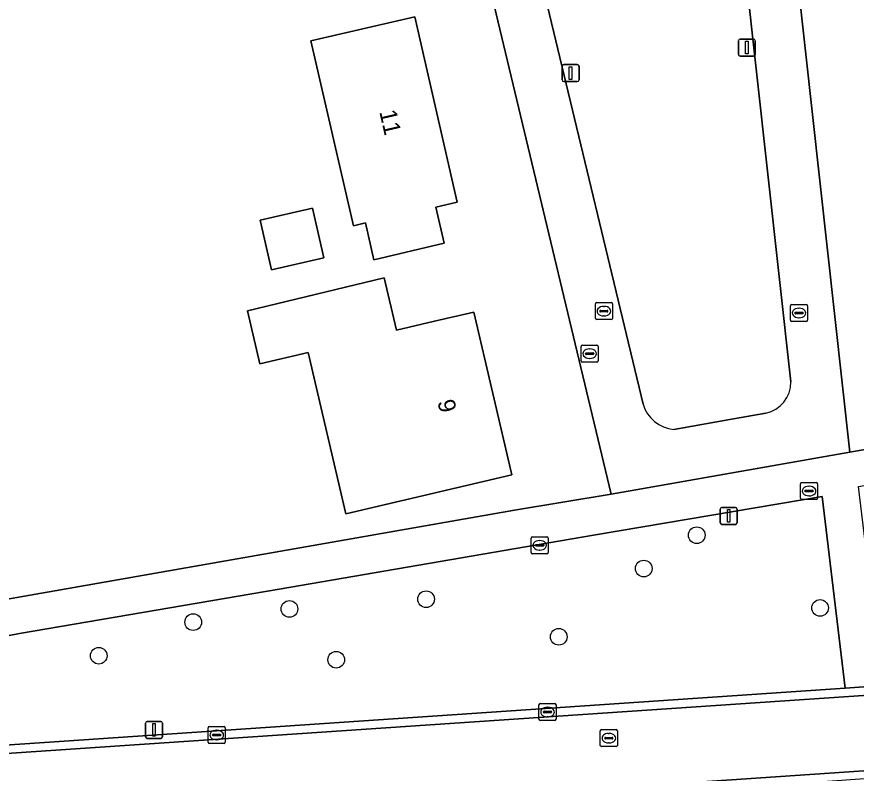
# Model space of a CAD drawing. Extents: x 162661 to 163484, y 380247 to 381230.
# Drawn here: x 162957.93 to 163007.21, y 380348.4 to 380392.8 of the extents above; entities that cross this region are included whole.
import ezdxf

# ---------------------------------------------------------------- set-up
doc = ezdxf.new("R2010")
doc.units = 0
for name, color, linetype in [('IMGEO_Boom', 7, 'Continuous'), ('IMGEO_Brandkraan', 7, 'Continuous'), ('IMGEO_Erf', 7, 'Continuous'), ('IMGEO_Groenvoorziening', 7, 'Continuous'), ('IMGEO_Kolk', 7, 'Continuous'), ('IMGEO_Lichtmast', 7, 'Continuous'), ('IMGEO_Pand', 7, 'Continuous'), ('IMGEO_Pand_nummerreeks', 7, 'Continuous'), ('IMGEO_Rijbaan_lokaal_gesloten', 7, 'Continuous'), ('IMGEO_Rijbaan_lokaal_open', 7, 'Continuous'), ('IMGEO_Rioolput', 7, 'Continuous'), ('IMGEO_Voetpad_open', 7, 'Continuous')]:
    doc.layers.add(name, color=color, linetype=linetype)

msp = doc.modelspace()

# ---------------------------------------------------------------- linework, layer by layer
at = {"layer": 'IMGEO_Boom'}
for centre in [(162997.848, 380362.374), (162994.736, 380360.416), (162981.956, 380358.616), (162973.936, 380358.043), (163005.09, 380358.105), (162968.286, 380357.27), (162989.744, 380356.409), (162962.74, 380355.298), (162976.682, 380355.067)]:
    msp.add_circle(centre, 0.489, dxfattribs=at)
at = {"layer": 'IMGEO_Brandkraan'}
for p, q in [((162991.059, 380372.602), (162991.059, 380373.454)), ((162991.134, 380373.528), (162991.986, 380373.528)), ((162991.547, 380373.308), (162991.572, 380373.308)), ((162992.06, 380373.454), (162992.06, 380372.602)), ((162991.318, 380373.022), (162991.318, 380373.034)), ((162991.756, 380372.985), (162991.358, 380372.985)), ((162991.361, 380373.071), (162991.759, 380373.071)), ((162991.802, 380373.034), (162991.802, 380373.022)), ((162991.986, 380372.528), (162991.134, 380372.528)), ((162991.57, 380372.748), (162991.545, 380372.748))]:
    msp.add_line(p, q, dxfattribs=at)
for points in [[(162991.059, 380372.602), (162991.059, 380373.454)], [(162991.134, 380373.528), (162991.986, 380373.528)], [(162992.06, 380373.454), (162992.06, 380372.602)], [(162991.986, 380372.528), (162991.134, 380372.528)]]:
    msp.add_lwpolyline(points, dxfattribs=at)
for centre, radius, start, end in [((162991.136, 380373.452), 0.0765, 91.552, 178.448), ((162991.136, 380373.452), 0.0765, 91.552, 178.448), ((162991.984, 380373.452), 0.0765, 1.552, 88.448), ((162991.984, 380373.452), 0.0765, 1.552, 88.448), ((162991.358, 380373.031), 0.0403, 85.8775, 175.7526), ((162991.355, 380373.021), 0.0366, 178.938, 274.7102), ((162991.759, 380373.028), 0.043, 264.8664, 352.4533), ((162991.763, 380373.033), 0.0386, 1.7309, 96.639), ((162991.136, 380372.604), 0.0765, 181.552, 268.448), ((162991.136, 380372.604), 0.0765, 181.552, 268.448), ((162991.984, 380372.604), 0.0765, 271.552, 358.448), ((162991.984, 380372.604), 0.0765, 271.552, 358.448)]:
    msp.add_arc(centre, radius, start, end, dxfattribs=at)
for centre, major_axis, ratio, start_param, end_param in [((162991.546, 380373.028), (-0.387, 0.002), 0.722429, 4.712389, 7.853982), ((162991.571, 380373.028), (-0.39, 0.002), 0.717154, 1.570796, 4.712389)]:
    msp.add_ellipse(centre, major_axis=major_axis, ratio=ratio, start_param=start_param, end_param=end_param, dxfattribs=at)
at = {"layer": 'IMGEO_Erf'}
for points in [[(163047.603, 380433.152), (163037.976, 380431.448), (163035.606, 380431.035), (163000.273, 380424.875), (163000.715, 380422.638), (163006.844, 380367.252), (163011.947, 380368.147), (163056.95, 380375.873)], [(162978.403, 380380.697), (162977.693, 380380.534), (162975.198, 380391.388), (162981.296, 380392.79), (162983.793, 380381.919), (162982.534, 380381.629), (162983.018, 380379.52), (162978.9, 380378.536)], [(162972.219, 380380.862), (162975.285, 380381.566), (162975.954, 380378.655), (162972.889, 380377.95)], [(162979.492, 380377.472), (162980.227, 380374.409), (162982.452, 380374.94), (162984.767, 380375.463), (162986.986, 380365.917), (162977.24, 380363.634), (162975.026, 380373.087), (162972.2, 380372.426), (162971.47, 380375.545)]]:
    msp.add_lwpolyline(points, close=True, dxfattribs=at)
msp.add_lwpolyline([(162943.939, 380397.468), (162945.155, 380386.295), (162946.371, 380375.13), (162945.703, 380375.057), (162945.909, 380373.16), (162946.16, 380370.851), (162946.868, 380370.928), (162948.049, 380360.077), (162951.696, 380360.474), (162952.002, 380357.671), (162987.152, 380363.833), (162992.818, 380364.786), (162980.426, 380416.595)], dxfattribs=at)
at = {"layer": 'IMGEO_Groenvoorziening'}
for points in [[(163003.383, 380371.369), (163000, 380401.781), (162997.93, 380419.975), (162997.616, 380422.36), (162997.043, 380422.281), (162983.247, 380419.922), (162982.667, 380419.816), (162983.47, 380416.805), (162994.695, 380370.063)], [(162996.513, 380368.584), (163000, 380369.199), (163001.901, 380369.535)], [(162940.787, 380348.935), (163006.568, 380353.401), (163005.21, 380364.635), (163000, 380363.76), (162991.897, 380362.399), (162989.055, 380361.908), (162973.327, 380359.209), (162958.085, 380356.605), (162953.727, 380355.77), (162950.999, 380355.403), (162937.978, 380353.182), (162938.144, 380351.678)]]:
    msp.add_lwpolyline(points, dxfattribs=at)
for centre, radius, start, end in [((163001.524, 380371.355), 1.859, 281.6989, 0.4199), ((162996.683, 380370.65), 2.073, 196.4576, 265.2836)]:
    msp.add_arc(centre, radius, start, end, dxfattribs=at)
at = {"layer": 'IMGEO_Kolk'}
for p, q in [((163003.944, 380364.537), (163003.944, 380365.389)), ((163004.019, 380365.463), (163004.871, 380365.463)), ((163004.945, 380365.389), (163004.945, 380364.537)), ((163004.203, 380364.957), (163004.203, 380364.969)), ((163004.641, 380364.92), (163004.243, 380364.92)), ((163004.246, 380365.006), (163004.644, 380365.006)), ((163004.432, 380365.243), (163004.457, 380365.243)), ((163004.687, 380364.969), (163004.687, 380364.957)), ((163004.871, 380364.463), (163004.019, 380364.463)), ((163004.455, 380364.683), (163004.43, 380364.683)), ((162988.125, 380361.355), (162988.125, 380362.207)), ((162988.2, 380362.281), (162989.052, 380362.281)), ((162988.613, 380362.061), (162988.638, 380362.061)), ((162989.126, 380362.207), (162989.126, 380361.355)), ((162988.384, 380361.775), (162988.384, 380361.787)), ((162988.822, 380361.738), (162988.424, 380361.738)), ((162988.427, 380361.824), (162988.825, 380361.824)), ((162988.636, 380361.501), (162988.611, 380361.501)), ((162988.868, 380361.787), (162988.868, 380361.775)), ((162989.052, 380361.281), (162988.2, 380361.281)), ((162988.587, 380351.568), (162988.587, 380352.42)), ((162988.662, 380352.494), (162989.514, 380352.494)), ((162989.075, 380352.274), (162989.1, 380352.274)), ((162989.588, 380352.42), (162989.588, 380351.568)), ((162988.846, 380351.988), (162988.846, 380352)), ((162989.284, 380351.951), (162988.886, 380351.951)), ((162988.889, 380352.037), (162989.287, 380352.037)), ((162989.098, 380351.714), (162989.073, 380351.714)), ((162989.33, 380352), (162989.33, 380351.988)), ((162969.242, 380351.144), (162970.094, 380351.144)), ((162989.514, 380351.494), (162988.662, 380351.494)), ((162969.167, 380350.218), (162969.167, 380351.07)), ((162969.426, 380350.638), (162969.426, 380350.65)), ((162969.864, 380350.601), (162969.466, 380350.601)), ((162969.469, 380350.687), (162969.867, 380350.687)), ((162969.655, 380350.924), (162969.68, 380350.924)), ((162969.91, 380350.65), (162969.91, 380350.638)), ((162970.168, 380351.07), (162970.168, 380350.218)), ((162970.094, 380350.144), (162969.242, 380350.144)), ((162969.678, 380350.364), (162969.653, 380350.364))]:
    msp.add_line(p, q, dxfattribs=at)
for points in [[(163003.944, 380364.537), (163003.944, 380365.389)], [(163004.019, 380365.463), (163004.871, 380365.463)], [(163004.945, 380365.389), (163004.945, 380364.537)], [(163004.871, 380364.463), (163004.019, 380364.463)], [(162988.125, 380361.355), (162988.125, 380362.207)], [(162988.2, 380362.281), (162989.052, 380362.281)], [(162989.126, 380362.207), (162989.126, 380361.355)], [(162989.052, 380361.281), (162988.2, 380361.281)], [(162988.587, 380351.568), (162988.587, 380352.42)], [(162988.662, 380352.494), (162989.514, 380352.494)], [(162989.588, 380352.42), (162989.588, 380351.568)], [(162969.242, 380351.144), (162970.094, 380351.144)], [(162989.514, 380351.494), (162988.662, 380351.494)], [(162969.167, 380350.218), (162969.167, 380351.07)], [(162970.168, 380351.07), (162970.168, 380350.218)], [(162970.094, 380350.144), (162969.242, 380350.144)]]:
    msp.add_lwpolyline(points, dxfattribs=at)
for centre, radius, start, end in [((163004.021, 380365.387), 0.0765, 91.552, 178.448), ((163004.021, 380365.387), 0.0765, 91.552, 178.448), ((163004.869, 380365.387), 0.0765, 1.552, 88.448), ((163004.869, 380365.387), 0.0765, 1.552, 88.448), ((163004.243, 380364.966), 0.0403, 85.8775, 175.7526), ((163004.24, 380364.956), 0.0366, 178.938, 274.7102), ((163004.644, 380364.963), 0.043, 264.8664, 352.4533), ((163004.648, 380364.968), 0.0386, 1.7309, 96.639), ((163004.021, 380364.539), 0.0765, 181.552, 268.448), ((163004.021, 380364.539), 0.0765, 181.552, 268.448), ((163004.869, 380364.539), 0.0765, 271.552, 358.448), ((163004.869, 380364.539), 0.0765, 271.552, 358.448), ((162988.202, 380362.205), 0.0765, 91.552, 178.448), ((162988.202, 380362.205), 0.0765, 91.552, 178.448), ((162989.05, 380362.205), 0.0765, 1.552, 88.448), ((162989.05, 380362.205), 0.0765, 1.552, 88.448), ((162988.424, 380361.784), 0.0403, 85.8775, 175.7526), ((162988.421, 380361.774), 0.0366, 178.938, 274.7102), ((162988.825, 380361.781), 0.043, 264.8664, 352.4533), ((162988.829, 380361.786), 0.0386, 1.7309, 96.639), ((162988.202, 380361.357), 0.0765, 181.552, 268.448), ((162988.202, 380361.357), 0.0765, 181.552, 268.448), ((162989.05, 380361.357), 0.0765, 271.552, 358.448), ((162989.05, 380361.357), 0.0765, 271.552, 358.448), ((162988.664, 380352.418), 0.0765, 91.552, 178.448), ((162988.664, 380352.418), 0.0765, 91.552, 178.448), ((162989.512, 380352.418), 0.0765, 1.552, 88.448), ((162989.512, 380352.418), 0.0765, 1.552, 88.448), ((162988.664, 380351.57), 0.0765, 181.552, 268.448), ((162988.664, 380351.57), 0.0765, 181.552, 268.448), ((162988.886, 380351.997), 0.0403, 85.8775, 175.7526), ((162988.883, 380351.987), 0.0366, 178.938, 274.7102), ((162989.287, 380351.994), 0.043, 264.8664, 352.4533), ((162989.291, 380351.999), 0.0386, 1.7309, 96.639), ((162989.512, 380351.57), 0.0765, 271.552, 358.448), ((162989.512, 380351.57), 0.0765, 271.552, 358.448), ((162969.244, 380351.068), 0.0765, 91.552, 178.448), ((162969.244, 380351.068), 0.0765, 91.552, 178.448), ((162970.092, 380351.068), 0.0765, 1.552, 88.448), ((162970.092, 380351.068), 0.0765, 1.552, 88.448), ((162969.466, 380350.647), 0.0403, 85.8775, 175.7526), ((162969.463, 380350.637), 0.0366, 178.938, 274.7102), ((162969.867, 380350.644), 0.043, 264.8664, 352.4533), ((162969.871, 380350.649), 0.0386, 1.7309, 96.639), ((162969.244, 380350.22), 0.0765, 181.552, 268.448), ((162969.244, 380350.22), 0.0765, 181.552, 268.448), ((162970.092, 380350.22), 0.0765, 271.552, 358.448), ((162970.092, 380350.22), 0.0765, 271.552, 358.448)]:
    msp.add_arc(centre, radius, start, end, dxfattribs=at)
for centre, major_axis, ratio, start_param, end_param in [((163004.431, 380364.963), (-0.387, 0.002), 0.722429, 4.712389, 7.853982), ((163004.456, 380364.963), (-0.39, 0.002), 0.717154, 1.570796, 4.712389), ((162988.612, 380361.781), (-0.387, 0.002), 0.722429, 4.712389, 7.853982), ((162988.637, 380361.781), (-0.39, 0.002), 0.717154, 1.570796, 4.712389), ((162989.074, 380351.994), (-0.387, 0.002), 0.722429, 4.712389, 7.853982), ((162989.099, 380351.994), (-0.39, 0.002), 0.717154, 1.570796, 4.712389), ((162969.654, 380350.644), (-0.387, 0.002), 0.722429, 4.712389, 7.853982), ((162969.679, 380350.644), (-0.39, 0.002), 0.717154, 1.570796, 4.712389)]:
    msp.add_ellipse(centre, major_axis=major_axis, ratio=ratio, start_param=start_param, end_param=end_param, dxfattribs=at)
at = {"layer": 'IMGEO_Lichtmast'}
for p, q in [((163000.395, 380391.493), (163001.185, 380391.493)), ((163001.185, 380391.493), (163000.395, 380391.493)), ((163000.295, 380390.593), (163000.295, 380391.393)), ((163000.295, 380391.393), (163000.295, 380390.593)), ((163001.285, 380391.393), (163001.285, 380390.593)), ((163001.285, 380390.593), (163001.285, 380391.393)), ((163001.185, 380390.493), (163000.395, 380390.493)), ((163000.395, 380390.493), (163001.185, 380390.493)), ((162989.948, 380389.091), (162989.948, 380389.891)), ((162989.948, 380389.891), (162989.948, 380389.091)), ((162990.048, 380389.991), (162990.838, 380389.991)), ((162990.838, 380389.991), (162990.048, 380389.991)), ((162990.938, 380389.891), (162990.938, 380389.091)), ((162990.938, 380389.091), (162990.938, 380389.891)), ((162990.838, 380388.991), (162990.048, 380388.991)), ((162990.048, 380388.991), (162990.838, 380388.991)), ((162999.226, 380363.106), (162999.226, 380363.906)), ((162999.226, 380363.906), (162999.226, 380363.106)), ((162999.326, 380364.006), (163000.116, 380364.006)), ((163000.116, 380364.006), (162999.326, 380364.006)), ((163000.216, 380363.906), (163000.216, 380363.106)), ((163000.216, 380363.106), (163000.216, 380363.906)), ((163000.116, 380363.006), (162999.326, 380363.006)), ((162999.326, 380363.006), (163000.116, 380363.006)), ((162965.488, 380350.546), (162965.488, 380351.346)), ((162965.488, 380351.346), (162965.488, 380350.546)), ((162965.588, 380351.446), (162966.378, 380351.446)), ((162966.378, 380351.446), (162965.588, 380351.446)), ((162966.478, 380351.346), (162966.478, 380350.546)), ((162966.478, 380350.546), (162966.478, 380351.346)), ((162966.378, 380350.446), (162965.588, 380350.446)), ((162965.588, 380350.446), (162966.378, 380350.446))]:
    msp.add_line(p, q, dxfattribs=at)
for points in [[(163000.715, 380391.368), (163000.865, 380391.368), (163000.865, 380390.618), (163000.715, 380390.618), (163000.715, 380391.368)], [(162990.368, 380389.866), (162990.518, 380389.866), (162990.518, 380389.116), (162990.368, 380389.116), (162990.368, 380389.866)], [(162999.646, 380363.881), (162999.796, 380363.881), (162999.796, 380363.131), (162999.646, 380363.131), (162999.646, 380363.881)], [(162965.908, 380351.321), (162966.058, 380351.321), (162966.058, 380350.571), (162965.908, 380350.571), (162965.908, 380351.321)]]:
    msp.add_lwpolyline(points, dxfattribs=at)
for centre, start, end in [((163000.395, 380391.393), 90, 180), ((163000.395, 380391.393), 90, 180), ((163001.185, 380391.393), 0, 90), ((163001.185, 380391.393), 360, 90), ((163000.395, 380390.593), 180, 270), ((163000.395, 380390.593), 180, 270), ((163001.185, 380390.593), 270, 0), ((163001.185, 380390.593), 270, 0), ((162990.048, 380389.891), 90, 180), ((162990.048, 380389.891), 90, 180), ((162990.838, 380389.891), 0, 90), ((162990.838, 380389.891), 360, 90), ((162990.048, 380389.091), 180, 270), ((162990.048, 380389.091), 180, 270), ((162990.838, 380389.091), 270, 0), ((162990.838, 380389.091), 270, 0), ((162999.326, 380363.906), 90, 180), ((162999.326, 380363.906), 90, 180), ((163000.116, 380363.906), 0, 90), ((163000.116, 380363.906), 360, 90), ((162999.326, 380363.106), 180, 270), ((162999.326, 380363.106), 180, 270), ((163000.116, 380363.106), 270, 0), ((163000.116, 380363.106), 270, 0), ((162965.588, 380351.346), 90, 180), ((162965.588, 380351.346), 90, 180), ((162966.378, 380351.346), 0, 90), ((162966.378, 380351.346), 360, 90), ((162965.588, 380350.546), 180, 270), ((162965.588, 380350.546), 180, 270), ((162966.378, 380350.546), 270, 0), ((162966.378, 380350.546), 270, 0)]:
    msp.add_arc(centre, 0.1, start, end, dxfattribs=at)
at = {"layer": 'IMGEO_Pand'}
for points in [[(162978.9, 380378.536), (162983.018, 380379.52), (162982.534, 380381.629), (162983.793, 380381.919), (162981.296, 380392.79), (162975.198, 380391.388), (162977.693, 380380.534), (162978.403, 380380.697)], [(162972.219, 380380.862), (162972.889, 380377.95), (162975.954, 380378.655), (162975.285, 380381.566)], [(162982.452, 380374.94), (162980.227, 380374.409), (162979.492, 380377.472), (162971.47, 380375.545), (162972.2, 380372.426), (162975.026, 380373.087), (162977.24, 380363.634), (162986.986, 380365.917), (162984.767, 380375.463)]]:
    msp.add_lwpolyline(points, close=True, dxfattribs=at)
at = {"layer": 'IMGEO_Rijbaan_lokaal_gesloten'}
msp.add_lwpolyline([(163054.493, 380356.141), (162940.821, 380348.438), (162934.53, 380348.012), (162935.401, 380343.628), (163028.95, 380349.989), (163129.435, 380356.95), (163129.13, 380361.35)], dxfattribs=at)
at = {"layer": 'IMGEO_Rijbaan_lokaal_open'}
for points in [[(162994.695, 380370.063), (162983.47, 380416.805), (162982.667, 380419.816), (162979.749, 380419.019), (162980.426, 380416.595), (162992.818, 380364.786), (163006.844, 380367.252), (163000.715, 380422.638)], [(163000.715, 380422.638), (162997.616, 380422.36), (162997.93, 380419.975), (163000, 380401.781), (163003.383, 380371.369)], [(163001.901, 380369.535), (163000, 380369.199), (162996.513, 380368.584)], [(163054.471, 380356.654), (163008.76, 380353.55), (163006.568, 380353.401), (162940.787, 380348.935), (162940.821, 380348.438), (163054.493, 380356.141)], [(163028.95, 380349.989), (162935.401, 380343.628), (162935.648, 380343.14), (162955.114, 380344.463), (162960.595, 380344.836), (162985.556, 380346.533), (162988.485, 380346.732), (162988.843, 380346.757), (162994.692, 380347.172), (162996.104, 380347.272), (162997.878, 380347.397), (162998.511, 380347.442), (163000.331, 380347.571), (163003.983, 380347.829), (163004.444, 380347.862), (163010.118, 380348.264)]]:
    msp.add_lwpolyline(points, dxfattribs=at)
for centre, radius, start, end in [((163001.524, 380371.355), 1.859, 281.6989, 0.4199), ((162996.683, 380370.65), 2.073, 196.4576, 265.2836)]:
    msp.add_arc(centre, radius, start, end, dxfattribs=at)
at = {"layer": 'IMGEO_Rioolput'}
for p, q in [((162991.896, 380375.098), (162991.896, 380375.95)), ((162991.971, 380376.024), (162992.823, 380376.024)), ((162992.384, 380375.804), (162992.409, 380375.804)), ((162992.897, 380375.95), (162992.897, 380375.098)), ((163003.353, 380374.989), (163003.353, 380375.841)), ((163003.428, 380375.915), (163004.28, 380375.915)), ((163004.354, 380375.841), (163004.354, 380374.989)), ((162992.155, 380375.518), (162992.155, 380375.53)), ((162992.593, 380375.481), (162992.195, 380375.481)), ((162992.198, 380375.567), (162992.596, 380375.567)), ((162992.407, 380375.244), (162992.382, 380375.244)), ((162992.639, 380375.53), (162992.639, 380375.518)), ((163003.612, 380375.409), (163003.612, 380375.421)), ((163004.05, 380375.372), (163003.652, 380375.372)), ((163003.655, 380375.458), (163004.053, 380375.458)), ((163003.841, 380375.695), (163003.866, 380375.695)), ((163004.096, 380375.421), (163004.096, 380375.409)), ((162992.823, 380375.024), (162991.971, 380375.024)), ((163004.28, 380374.915), (163003.428, 380374.915)), ((163003.864, 380375.135), (163003.839, 380375.135)), ((162992.188, 380350.038), (162992.188, 380350.89)), ((162992.263, 380350.964), (162993.115, 380350.964)), ((162992.676, 380350.744), (162992.701, 380350.744)), ((162993.189, 380350.89), (162993.189, 380350.038)), ((162992.447, 380350.458), (162992.447, 380350.47)), ((162992.885, 380350.421), (162992.487, 380350.421)), ((162992.49, 380350.507), (162992.888, 380350.507)), ((162992.699, 380350.184), (162992.674, 380350.184)), ((162992.931, 380350.47), (162992.931, 380350.458)), ((162993.115, 380349.964), (162992.263, 380349.964))]:
    msp.add_line(p, q, dxfattribs=at)
for points in [[(162991.896, 380375.098), (162991.896, 380375.95)], [(162991.971, 380376.024), (162992.823, 380376.024)], [(162992.897, 380375.95), (162992.897, 380375.098)], [(163003.353, 380374.989), (163003.353, 380375.841)], [(163003.428, 380375.915), (163004.28, 380375.915)], [(163004.354, 380375.841), (163004.354, 380374.989)], [(162992.823, 380375.024), (162991.971, 380375.024)], [(163004.28, 380374.915), (163003.428, 380374.915)], [(162992.188, 380350.038), (162992.188, 380350.89)], [(162992.263, 380350.964), (162993.115, 380350.964)], [(162993.189, 380350.89), (162993.189, 380350.038)], [(162993.115, 380349.964), (162992.263, 380349.964)]]:
    msp.add_lwpolyline(points, dxfattribs=at)
for centre, radius, start, end in [((162991.973, 380375.948), 0.0765, 91.552, 178.448), ((162991.973, 380375.948), 0.0765, 91.552, 178.448), ((162992.821, 380375.948), 0.0765, 1.552, 88.448), ((162992.821, 380375.948), 0.0765, 1.552, 88.448), ((163003.43, 380375.839), 0.0765, 91.552, 178.448), ((163003.43, 380375.839), 0.0765, 91.552, 178.448), ((163004.278, 380375.839), 0.0765, 1.552, 88.448), ((163004.278, 380375.839), 0.0765, 1.552, 88.448), ((162992.195, 380375.527), 0.0403, 85.8775, 175.7526), ((162992.192, 380375.517), 0.0366, 178.938, 274.7102), ((162992.596, 380375.524), 0.043, 264.8664, 352.4533), ((162992.6, 380375.529), 0.0386, 1.7309, 96.639), ((163003.652, 380375.418), 0.0403, 85.8775, 175.7526), ((163003.649, 380375.408), 0.0366, 178.938, 274.7102), ((163004.053, 380375.415), 0.043, 264.8664, 352.4533), ((163004.057, 380375.42), 0.0386, 1.7309, 96.639), ((162991.973, 380375.1), 0.0765, 181.552, 268.448), ((162991.973, 380375.1), 0.0765, 181.552, 268.448), ((162992.821, 380375.1), 0.0765, 271.552, 358.448), ((162992.821, 380375.1), 0.0765, 271.552, 358.448), ((163003.43, 380374.991), 0.0765, 181.552, 268.448), ((163003.43, 380374.991), 0.0765, 181.552, 268.448), ((163004.278, 380374.991), 0.0765, 271.552, 358.448), ((163004.278, 380374.991), 0.0765, 271.552, 358.448), ((162992.265, 380350.888), 0.0765, 91.552, 178.448), ((162992.265, 380350.888), 0.0765, 91.552, 178.448), ((162993.113, 380350.888), 0.0765, 1.552, 88.448), ((162993.113, 380350.888), 0.0765, 1.552, 88.448), ((162992.487, 380350.467), 0.0403, 85.8775, 175.7526), ((162992.484, 380350.457), 0.0366, 178.938, 274.7102), ((162992.888, 380350.464), 0.043, 264.8664, 352.4533), ((162992.892, 380350.469), 0.0386, 1.7309, 96.639), ((162992.265, 380350.04), 0.0765, 181.552, 268.448), ((162992.265, 380350.04), 0.0765, 181.552, 268.448), ((162993.113, 380350.04), 0.0765, 271.552, 358.448), ((162993.113, 380350.04), 0.0765, 271.552, 358.448)]:
    msp.add_arc(centre, radius, start, end, dxfattribs=at)
for centre, major_axis, ratio, start_param, end_param in [((162992.383, 380375.524), (-0.387, 0.002), 0.722429, 4.712389, 7.853982), ((162992.408, 380375.524), (-0.39, 0.002), 0.717154, 1.570796, 4.712389), ((163003.84, 380375.415), (-0.387, 0.002), 0.722429, 4.712389, 7.853982), ((163003.865, 380375.415), (-0.39, 0.002), 0.717154, 1.570796, 4.712389), ((162992.675, 380350.464), (-0.387, 0.002), 0.722429, 4.712389, 7.853982), ((162992.7, 380350.464), (-0.39, 0.002), 0.717154, 1.570796, 4.712389)]:
    msp.add_ellipse(centre, major_axis=major_axis, ratio=ratio, start_param=start_param, end_param=end_param, dxfattribs=at)
at = {"layer": 'IMGEO_Voetpad_open'}
msp.add_lwpolyline([(163005.21, 380364.635), (163006.568, 380353.401), (163008.76, 380353.55), (163007.348, 380365.222), (163057.264, 380373.948), (163056.95, 380375.873), (163011.947, 380368.147), (163006.844, 380367.252), (162992.818, 380364.786), (162987.152, 380363.833), (162952.002, 380357.671), (162951.261, 380357.59), (162937.748, 380355.281), (162937.978, 380353.182), (162950.999, 380355.403), (162953.727, 380355.77), (162958.085, 380356.605), (162973.327, 380359.209), (162989.055, 380361.908), (162991.897, 380362.399), (163000, 380363.76)], close=True, dxfattribs=at)

# ---------------------------------------------------------------- texts
at = {"layer": 'IMGEO_Pand_nummerreeks'}
for s, rotation, p in [('11', 282.9361, (162979.208, 380387.226)), ('9', 283.0862, (162982.62, 380370.215))]:
    msp.add_text(s, height=1, rotation=rotation, dxfattribs=at).set_placement(p)

doc.saveas('drawing.dxf')
